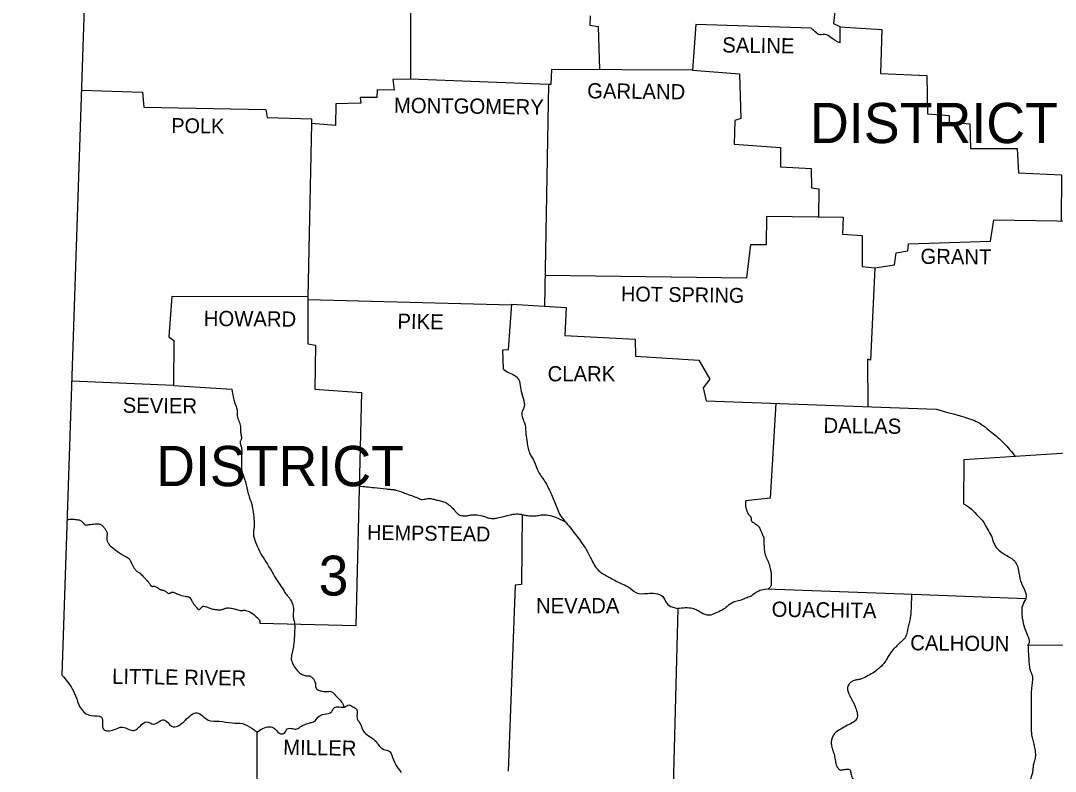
# Model space of a CAD drawing. Extents: x 6028666 to 6031787, y 5366484 to 5368484.
# Drawn here: x 6031108.5 to 6031401.8, y 5367817 to 5368029.7 of the extents above; entities that cross this region are included whole.
import ezdxf

# ---------------------------------------------------------------- set-up
doc = ezdxf.new("R2010")
doc.units = 0
doc.layers.add('2', color=7, linetype='Continuous')

msp = doc.modelspace()

# ---------------------------------------------------------------- linework, layer by layer
at = {"layer": '2'}
msp.add_line((6031258.15, 5368011.6), (6031256.99, 5367948.8), dxfattribs=at)
for points in [[(6031108.45, 5368281.69), (6031129.15, 5368115.5), (6031120.15, 5367844.2)], [(6031219.09, 5368054.06), (6031218.95, 5368013.1), (6031213.95, 5368013), (6031214.35, 5368010), (6031209.55, 5368010.1), (6031209.45, 5368007.9), (6031204.75, 5368007.9), (6031204.85, 5368006.3), (6031197.85, 5368006.1), (6031197.75, 5368000), (6031190.95, 5368000.6), (6031189.85, 5367951.4), (6031151.35, 5367951.5), (6031150.45, 5367940.1), (6031151.85, 5367939.1), (6031151.75, 5367926.3), (6031122.92, 5367927.57)], [(6031372.35, 5368042.9), (6031365.15, 5368043.7), (6031365.45, 5368041), (6031352.35, 5368040.5), (6031351.95, 5368036.6), (6031339.65, 5368035.9), (6031338.95, 5368028.9), (6031340.75, 5368028), (6031340.75, 5368023.4)], [(6031269.95, 5368031.1), (6031269.85, 5368028.4), (6031272.15, 5368028), (6031272.57, 5368015.83)], [(6031332.55, 5368027.6), (6031299.85, 5368028.6), (6031298.95, 5368015.7), (6031258.95, 5368015.9), (6031258.79, 5368011.57)], [(6031340.75, 5368027.94), (6031352.65, 5368027.2), (6031352.25, 5368014.7), (6031365.35, 5368014.2), (6031365.55, 5368003.3), (6031371.75, 5368002.8), (6031371.75, 5368000.9), (6031377.55, 5368000.5), (6031377.75, 5367993.5), (6031390.95, 5367993.5), (6031391.35, 5367986.6), (6031403.55, 5367986), (6031403.45, 5367972.98)], [(6031298.95, 5368015.7), (6031312.25, 5368014.6), (6031312.65, 5368002), (6031310.95, 5368001.4), (6031310.75, 5367994.7), (6031323.85, 5367993.8), (6031323.85, 5367988.3), (6031332.55, 5367987.8), (6031332.65, 5367982.3), (6031334.75, 5367982), (6031334.65, 5367974.1)], [(6031258.15, 5368011.6), (6031218.95, 5368013.1)], [(6031125.65, 5368010), (6031142.95, 5368009.4), (6031143.35, 5368005.2), (6031177.95, 5368004.5), (6031178.35, 5368002.3), (6031190.95, 5368001.9), (6031190.95, 5368000.6)], [(6031258.79, 5368011.57), (6031258.15, 5368011.6)], [(6031257.15, 5367957.6), (6031314.35, 5367956.8), (6031315.45, 5367966.3), (6031319.95, 5367966.3), (6031320.05, 5367974.3), (6031341.65, 5367974), (6031341.45, 5367969.2), (6031347.05, 5367968.8), (6031347.05, 5367960), (6031350.65, 5367959.7), (6031350.61, 5367958.79)], [(6031350.65, 5367959.7), (6031356.25, 5367960.5), (6031356.65, 5367963.9), (6031359.95, 5367964.5), (6031360.15, 5367966.5), (6031383.45, 5367967.2), (6031384.35, 5367973.3), (6031408.25, 5367972.9)], [(6031350.65, 5367959.7), (6031349.45, 5367933.5), (6031348.55, 5367933.8), (6031348.65, 5367920.32)], [(6031189.85, 5367951.4), (6031189.85, 5367938.1), (6031192.05, 5367937.7), (6031191.85, 5367925.3), (6031205.05, 5367924.3), (6031203.45, 5367858.2), (6031176.25, 5367858.9)], [(6031189.85, 5367950.71), (6031247.74, 5367949.19)], [(6031245.35, 5367930.9), (6031245.15, 5367936.4), (6031246.75, 5367936.5), (6031247.75, 5367949.4), (6031263.15, 5367948.4), (6031262.75, 5367940.5), (6031282.65, 5367939.4), (6031282.75, 5367934.6), (6031300.75, 5367933.5), (6031303.85, 5367928.1), (6031301.95, 5367925.7), (6031302.85, 5367922), (6031368.05, 5367919.6)], [(6031151.75, 5367926.3), (6031168.35, 5367925.3)], [(6031322.52, 5367921.28), (6031320.95, 5367894.4), (6031314.05, 5367893.6)], [(6031390.49, 5367906.2), (6031375.85, 5367905.3), (6031375.75, 5367892.8)], [(6031405.05, 5367907.1), (6031390.43, 5367906.2)], [(6031250.65, 5367889.75), (6031250.45, 5367869.9), (6031248.65, 5367869.7), (6031246.65, 5367817)], [(6031319.95, 5367868.7), (6031361.35, 5367867.2), (6031393.47, 5367865.95)], [(6031294.75, 5367863.1), (6031293.45, 5367812.7), (6031279.95, 5367813.6), (6031279.85, 5367809.9), (6031262.06, 5367810.95)], [(6031394.05, 5367852.7), (6031439.25, 5367852.8)], [(6031175.45, 5367828.1), (6031175.65, 5367747.21), (6031542.15, 5367746.61)]]:
    msp.add_lwpolyline(points, dxfattribs=at)
for points in [[(6031340.75, 5368023.4), (6031338.15, 5368024.9), (6031336.65, 5368025.8), (6031335.05, 5368025.7), (6031333.75, 5368026.5), (6031332.55, 5368027.6)], [(6031245.35, 5367930.9), (6031246.95, 5367929.9), (6031248.85, 5367929), (6031249.85, 5367927.5), (6031250.25, 5367925.2), (6031250.95, 5367922.7), (6031251.15, 5367920.1), (6031250.55, 5367918.7), (6031251.35, 5367915.5), (6031251.65, 5367913.3), (6031251.95, 5367910.7), (6031252.75, 5367907.2), (6031254.05, 5367904.8), (6031255.25, 5367901.9), (6031257.25, 5367898.8), (6031258.95, 5367895.4), (6031259.75, 5367893.6), (6031261.25, 5367889.9), (6031263.15, 5367887.4), (6031266.15, 5367883.6), (6031268.85, 5367879.7), (6031270.35, 5367876.8), (6031272.65, 5367873.6), (6031275.25, 5367872), (6031278.55, 5367870.3), (6031280.65, 5367869.3), (6031283.05, 5367867.6), (6031286.15, 5367867.4), (6031288.45, 5367867.4), (6031290.55, 5367866.5), (6031291.55, 5367864.7), (6031293.35, 5367863.5), (6031294.75, 5367863.1)], [(6031168.35, 5367925.3), (6031168.85, 5367922.3), (6031169.04, 5367921.64), (6031169.3, 5367921), (6031169.55, 5367920.36), (6031169.75, 5367919.7), (6031169.81, 5367919.21), (6031169.82, 5367918.7), (6031169.81, 5367918.2), (6031169.85, 5367917.7), (6031170.05, 5367916.95), (6031170.33, 5367916.21), (6031170.59, 5367915.46), (6031170.75, 5367914.7), (6031170.75, 5367913.6), (6031170.81, 5367913.05), (6031170.91, 5367912.5), (6031171, 5367911.95), (6031171.05, 5367911.4), (6031171, 5367911.1), (6031170.86, 5367910.8), (6031170.72, 5367910.5), (6031170.65, 5367910.2), (6031170.74, 5367909.61), (6031170.92, 5367909.01), (6031171.09, 5367908.41), (6031171.15, 5367907.8), (6031171.05, 5367906), (6031171.05, 5367904.5), (6031171.15, 5367902), (6031171.29, 5367901.44), (6031171.52, 5367900.89), (6031171.76, 5367900.35), (6031171.95, 5367899.8), (6031172.75, 5367896.5), (6031173.25, 5367894.8), (6031174.05, 5367892.2), (6031174.55, 5367889), (6031174.65, 5367886.6), (6031174.62, 5367886.05), (6031174.54, 5367885.5), (6031174.47, 5367884.95), (6031174.45, 5367884.4), (6031175.05, 5367881.9), (6031176.15, 5367879.4), (6031177.55, 5367877), (6031179.25, 5367874.3), (6031180.45, 5367872.2), (6031181.95, 5367869.9), (6031183.15, 5367868), (6031183.58, 5367867.39), (6031184.04, 5367866.81), (6031184.51, 5367866.22), (6031184.95, 5367865.6), (6031185.75, 5367863.6), (6031185.8, 5367862.9), (6031185.77, 5367862.2), (6031185.73, 5367861.5), (6031185.75, 5367860.8), (6031185.85, 5367860.15), (6031185.98, 5367859.51), (6031186.1, 5367858.86), (6031186.15, 5367858.2), (6031186.05, 5367855.3), (6031185.85, 5367852.7), (6031185.71, 5367851.8), (6031185.49, 5367850.9), (6031185.28, 5367850), (6031185.15, 5367849.1), (6031185.65, 5367847.4), (6031187.55, 5367844.9), (6031188.75, 5367844.2), (6031189.27, 5367844.08), (6031189.81, 5367844.06), (6031190.35, 5367844.01), (6031190.85, 5367843.8), (6031191.44, 5367843.16), (6031191.85, 5367842.4), (6031192, 5367841.88), (6031192.05, 5367841.3), (6031192.14, 5367840.76), (6031192.26, 5367840.52), (6031192.45, 5367840.3), (6031193.47, 5367839.81), (6031194.55, 5367839.6), (6031194.85, 5367839.57), (6031195.15, 5367839.58), (6031195.78, 5367839.65), (6031196.37, 5367839.65), (6031196.85, 5367839.4), (6031197.95, 5367838.2), (6031199.45, 5367836.6), (6031200.19, 5367835.2)], [(6031368.05, 5367919.6), (6031375.85, 5367917.4), (6031379.85, 5367915.9), (6031383.85, 5367913), (6031387.15, 5367910.1), (6031390.43, 5367906.2)], [(6031204.41, 5367897.8), (6031208.65, 5367897.4), (6031212.15, 5367897), (6031213.51, 5367896.89), (6031214.18, 5367896.83), (6031214.52, 5367896.77), (6031214.85, 5367896.7), (6031215.57, 5367896.49), (6031216.27, 5367896.24), (6031217.65, 5367895.7), (6031220.15, 5367894.8), (6031220.56, 5367894.64), (6031220.95, 5367894.45), (6031221.34, 5367894.26), (6031221.75, 5367894.1), (6031222.42, 5367894.03), (6031223.1, 5367894.15), (6031223.78, 5367894.29), (6031224.45, 5367894.3), (6031225.61, 5367894.08), (6031226.75, 5367893.8), (6031228.09, 5367893.45), (6031228.73, 5367893.22), (6031229.05, 5367893.07), (6031229.35, 5367892.9), (6031230.36, 5367892.1), (6031231.25, 5367891.2), (6031231.54, 5367890.88), (6031231.81, 5367890.54), (6031232.45, 5367889.9), (6031233.01, 5367889.6), (6031233.59, 5367889.45), (6031234.75, 5367889.4), (6031235.23, 5367889.46), (6031235.7, 5367889.56), (6031236.18, 5367889.66), (6031236.65, 5367889.7), (6031238.95, 5367889.5), (6031239.61, 5367889.33), (6031240.26, 5367889.08), (6031240.9, 5367888.85), (6031241.55, 5367888.7), (6031242.08, 5367888.66), (6031242.61, 5367888.66), (6031243.65, 5367888.8), (6031245.35, 5367889.2), (6031247.35, 5367889.7), (6031248.6, 5367889.9), (6031249.23, 5367889.92), (6031249.85, 5367889.9), (6031250.33, 5367889.83), (6031250.8, 5367889.71), (6031251.27, 5367889.59), (6031251.75, 5367889.5), (6031253, 5367889.42), (6031254.25, 5367889.4), (6031254.98, 5367889.46), (6031255.7, 5367889.58), (6031256.43, 5367889.68), (6031256.79, 5367889.71), (6031257.15, 5367889.7), (6031257.89, 5367889.61), (6031260.07, 5367888.98), (6031261.49, 5367888.37), (6031262.88, 5367887.74)], [(6031314.05, 5367893.6), (6031313.94, 5367892.65), (6031313.98, 5367892.17), (6031314.05, 5367891.7), (6031314.17, 5367891.24), (6031314.33, 5367890.78), (6031314.53, 5367890.34), (6031314.75, 5367889.9), (6031314.91, 5367889.68), (6031315.1, 5367889.49), (6031315.29, 5367889.31), (6031315.45, 5367889.1), (6031315.55, 5367888.79), (6031315.57, 5367888.43), (6031315.6, 5367888.09), (6031315.66, 5367887.93), (6031315.75, 5367887.8), (6031315.96, 5367887.63), (6031316.2, 5367887.49), (6031316.43, 5367887.36), (6031316.65, 5367887.2), (6031316.83, 5367887.07), (6031317.01, 5367886.93), (6031317.37, 5367886.66), (6031317.7, 5367886.36), (6031317.84, 5367886.19), (6031317.95, 5367886), (6031318.15, 5367885.58), (6031318.32, 5367885.16), (6031318.48, 5367884.73), (6031318.65, 5367884.3), (6031318.92, 5367883.76), (6031319.05, 5367883.49), (6031319.11, 5367883.35), (6031319.15, 5367883.2), (6031319.2, 5367882.85), (6031319.19, 5367882.5), (6031319.16, 5367882.15), (6031319.15, 5367881.8), (6031319.2, 5367881.1), (6031319.25, 5367880.4), (6031319.33, 5367879.55), (6031319.38, 5367879.13), (6031319.45, 5367878.7), (6031319.68, 5367877.93), (6031320.02, 5367877.19), (6031320.37, 5367876.46), (6031320.65, 5367875.7), (6031320.95, 5367874.5), (6031321.15, 5367873.5), (6031321.25, 5367871.8), (6031321.27, 5367871.3), (6031321.28, 5367870.8), (6031321.27, 5367870.3), (6031321.27, 5367870.05), (6031321.25, 5367869.8), (6031321.17, 5367869.52), (6031320.97, 5367869.21), (6031320.43, 5367868.69)], [(6031375.75, 5367892.8), (6031378.05, 5367891.3), (6031379.95, 5367889.3), (6031381.35, 5367887.8), (6031382.25, 5367886.1), (6031383.45, 5367884.1), (6031385.15, 5367880.3), (6031386.65, 5367879), (6031388.75, 5367877.7), (6031390.05, 5367876.8), (6031391.35, 5367873.9), (6031391.95, 5367871), (6031393.05, 5367868.4), (6031393.55, 5367866.4), (6031392.65, 5367864.4), (6031392.45, 5367860.4), (6031393.05, 5367857.7), (6031393.85, 5367855.7), (6031394.35, 5367853.4), (6031394.05, 5367852.7)], [(6031121.62, 5367888.34), (6031122.63, 5367888.43), (6031123.66, 5367888.41), (6031124.63, 5367888.3), (6031125.45, 5367888.1), (6031125.81, 5367887.82), (6031126.15, 5367887.37), (6031126.52, 5367886.96), (6031126.95, 5367886.8), (6031127.85, 5367886.9), (6031129.45, 5367887.1), (6031129.83, 5367887.13), (6031130.2, 5367887.13), (6031130.58, 5367887.09), (6031130.95, 5367887), (6031131.28, 5367886.85), (6031131.56, 5367886.64), (6031131.81, 5367886.39), (6031132.05, 5367886.1), (6031132.36, 5367885.72), (6031132.62, 5367885.34), (6031132.83, 5367884.94), (6031132.95, 5367884.5), (6031132.97, 5367884.13), (6031132.92, 5367883.75), (6031132.86, 5367883.38), (6031132.85, 5367883), (6031132.95, 5367882.4), (6031133.07, 5367882.04), (6031133.22, 5367881.7), (6031133.65, 5367881.1), (6031134.85, 5367880.1), (6031136.15, 5367879.1), (6031137.35, 5367878.3), (6031137.61, 5367878.15), (6031137.9, 5367878.01), (6031138.47, 5367877.75), (6031138.98, 5367877.44), (6031139.35, 5367877), (6031139.55, 5367876.6), (6031140.35, 5367875), (6031140.8, 5367874.31), (6031141.06, 5367874), (6031141.35, 5367873.7), (6031141.64, 5367873.48), (6031141.96, 5367873.3), (6031142.27, 5367873.12), (6031142.55, 5367872.9), (6031143.85, 5367871.5), (6031144.45, 5367870.9), (6031144.72, 5367870.57), (6031144.94, 5367870.19), (6031145.17, 5367869.83), (6031145.3, 5367869.66), (6031145.45, 5367869.5), (6031145.7, 5367869.4), (6031145.99, 5367869.42), (6031146.28, 5367869.45), (6031146.55, 5367869.4), (6031146.93, 5367869.19), (6031147.3, 5367868.94), (6031147.67, 5367868.7), (6031148.05, 5367868.5), (6031148.32, 5367868.41), (6031148.61, 5367868.35), (6031148.89, 5367868.28), (6031149.15, 5367868.2), (6031149.46, 5367868.03), (6031149.75, 5367867.8), (6031150.04, 5367867.57), (6031150.35, 5367867.4), (6031150.65, 5367867.43), (6031150.95, 5367867.61), (6031151.26, 5367867.78), (6031151.55, 5367867.8), (6031151.93, 5367867.66), (6031152.3, 5367867.5), (6031152.68, 5367867.34), (6031153.05, 5367867.2), (6031155.05, 5367866.6), (6031155.33, 5367866.56), (6031155.62, 5367866.55), (6031156.03, 5367866.47), (6031156.09, 5367866.44), (6031156.15, 5367866.4), (6031156.57, 5367865.99), (6031156.88, 5367865.51), (6031157.15, 5367864.99), (6031157.29, 5367864.74), (6031157.45, 5367864.5), (6031158.07, 5367863.68), (6031158.4, 5367863.28), (6031158.75, 5367862.9), (6031158.93, 5367862.82), (6031159.11, 5367862.88), (6031159.51, 5367863.23), (6031159.92, 5367863.64), (6031160.14, 5367863.78), (6031160.35, 5367863.8), (6031161.09, 5367863.61), (6031161.84, 5367863.34), (6031162.59, 5367863.07), (6031163.35, 5367862.9), (6031164.31, 5367862.8), (6031165.25, 5367862.8), (6031165.68, 5367862.9), (6031166.1, 5367863.06), (6031166.52, 5367863.22), (6031166.95, 5367863.3), (6031168.25, 5367863.2), (6031168.86, 5367863.07), (6031169.45, 5367862.9), (6031170.05, 5367862.73), (6031170.65, 5367862.6), (6031171.02, 5367862.58), (6031171.4, 5367862.6), (6031171.78, 5367862.63), (6031172.15, 5367862.6), (6031173.75, 5367862), (6031175.25, 5367860.8), (6031176.25, 5367859.5), (6031176.25, 5367858.9)], [(6031315.45, 5367866.6), (6031314.73, 5367866.31), (6031313.45, 5367865.8), (6031311.95, 5367865.3), (6031310.55, 5367864.9), (6031308.75, 5367863.7), (6031307.35, 5367862.7), (6031305.45, 5367861.8), (6031303.65, 5367861.2), (6031301.45, 5367861.9), (6031300.25, 5367862.6), (6031298.95, 5367863.1), (6031294.75, 5367863.1)], [(6031315.45, 5367866.6), (6031318.05, 5367868.3), (6031319.95, 5367868.7)], [(6031361.02, 5367867.21), (6031360.95, 5367864.11), (6031360.88, 5367862.55), (6031360.83, 5367861.78), (6031360.75, 5367861), (6031360.45, 5367859.44), (6031360.05, 5367857.9), (6031359.79, 5367856.48), (6031359.62, 5367855.78), (6031359.5, 5367855.44), (6031359.43, 5367855.27), (6031359.35, 5367855.1), (6031359.05, 5367854.64), (6031358.67, 5367854.24), (6031357.85, 5367853.5), (6031357.05, 5367852.71), (6031356.25, 5367851.9), (6031354.75, 5367850.1), (6031354.41, 5367849.57), (6031354.11, 5367849), (6031353.8, 5367848.44), (6031353.45, 5367847.9), (6031352.15, 5367846.5), (6031350.45, 5367845.1), (6031348.75, 5367844.1), (6031346.85, 5367843.2), (6031346.34, 5367843.04), (6031345.81, 5367842.94), (6031345.28, 5367842.85), (6031344.75, 5367842.7), (6031343.92, 5367842.28), (6031343.56, 5367841.98), (6031343.4, 5367841.8), (6031343.25, 5367841.6), (6031342.99, 5367841.02), (6031342.9, 5367840.4), (6031343.15, 5367839.2), (6031343.56, 5367838.35), (6031344.01, 5367837.51), (6031344.45, 5367836.67), (6031344.85, 5367835.8), (6031345.45, 5367834.2), (6031345.59, 5367833.74), (6031345.67, 5367833.26), (6031345.7, 5367832.78), (6031345.65, 5367832.3), (6031344.95, 5367831.2), (6031343.35, 5367830.3), (6031341.45, 5367829.2), (6031339.75, 5367828.2), (6031339.35, 5367827.88), (6031339.02, 5367827.47), (6031338.76, 5367827), (6031338.55, 5367826.5), (6031338.28, 5367825.35), (6031338.35, 5367824.2), (6031338.54, 5367823.53), (6031338.75, 5367822.85), (6031338.97, 5367822.18), (6031339.15, 5367821.5), (6031339.3, 5367820.71), (6031339.45, 5367819.9), (6031339.84, 5367818.49), (6031340.19, 5367817.87), (6031340.44, 5367817.61), (6031340.59, 5367817.5), (6031340.75, 5367817.4), (6031341, 5367817.35), (6031341.25, 5367817.39), (6031341.5, 5367817.46), (6031341.75, 5367817.5), (6031341.98, 5367817.52), (6031342.2, 5367817.55), (6031342.66, 5367817.62), (6031343.11, 5367817.6), (6031343.33, 5367817.53), (6031343.44, 5367817.48), (6031343.55, 5367817.4), (6031343.7, 5367817.17), (6031343.75, 5367816.9), (6031343.85, 5367816.4), (6031344.25, 5367815.1), (6031344.55, 5367814.77), (6031345, 5367814.55), (6031345.45, 5367814.33), (6031345.75, 5367814), (6031345.82, 5367813.76), (6031345.86, 5367813.51), (6031345.89, 5367813.25), (6031345.95, 5367813), (6031346.33, 5367812.03), (6031346.85, 5367811.1), (6031347.17, 5367810.7), (6031347.52, 5367810.34), (6031348.35, 5367809.8), (6031349.45, 5367809.4), (6031351.75, 5367808.7), (6031352.95, 5367808.4), (6031353.12, 5367808.32), (6031353.44, 5367807.84), (6031353.59, 5367806.87), (6031353.75, 5367805.95), (6031353.94, 5367805.64), (6031354.25, 5367805.5), (6031355.05, 5367805.51), (6031355.85, 5367805.6), (6031357.05, 5367805.8), (6031358.06, 5367805.76), (6031358.56, 5367805.59), (6031358.81, 5367805.46), (6031359.05, 5367805.3), (6031359.59, 5367804.74), (6031359.95, 5367804.1), (6031360.19, 5367803.61), (6031360.4, 5367803.11), (6031360.61, 5367802.6), (6031360.85, 5367802.1), (6031361.38, 5367801.34), (6031361.66, 5367801.04)], [(6031394.05, 5367852.7), (6031394.13, 5367851.15), (6031394.22, 5367849.6), (6031394.45, 5367846.5), (6031394.63, 5367845.74), (6031394.94, 5367845), (6031395.23, 5367844.26), (6031395.32, 5367843.89), (6031395.35, 5367843.5), (6031395.31, 5367842.71), (6031395.21, 5367841.91), (6031395.12, 5367841.11), (6031395.05, 5367840.3), (6031394.95, 5367837.2), (6031394.95, 5367834.4), (6031394.95, 5367831.7), (6031394.95, 5367828.9), (6031395.15, 5367826.9), (6031395.3, 5367826.17), (6031395.49, 5367825.45), (6031395.68, 5367824.73), (6031395.85, 5367824), (6031396.1, 5367822.65), (6031396.16, 5367821.98), (6031396.15, 5367821.3), (6031396.05, 5367820.65), (6031395.88, 5367820), (6031395.7, 5367819.35), (6031395.55, 5367818.7), (6031395.48, 5367818.11), (6031395.43, 5367817.5), (6031395.36, 5367816.9), (6031395.25, 5367816.3), (6031395.07, 5367815.7), (6031394.86, 5367815.1), (6031394.64, 5367814.51), (6031394.45, 5367813.9), (6031393.75, 5367811.2), (6031392.95, 5367807.7), (6031392.64, 5367806.54), (6031392.46, 5367805.97), (6031392.25, 5367805.4), (6031391.95, 5367804.78), (6031391.58, 5367804.19), (6031391.2, 5367803.6), (6031390.85, 5367803), (6031390.61, 5367802.46), (6031390.4, 5367801.91), (6031390.19, 5367801.35), (6031389.95, 5367800.8), (6031389.64, 5367800.43), (6031389.23, 5367800.13), (6031388.82, 5367799.82), (6031388.66, 5367799.63), (6031388.55, 5367799.4), (6031388.33, 5367798.21), (6031388.35, 5367797), (6031388.42, 5367796.45), (6031388.51, 5367795.9), (6031388.6, 5367795.35), (6031388.65, 5367794.8), (6031388.63, 5367794.31), (6031388.56, 5367793.81), (6031388.48, 5367793.3), (6031388.45, 5367792.8), (6031388.63, 5367791.84), (6031389.15, 5367790.9), (6031389.49, 5367790.5), (6031389.85, 5367790.11), (6031390.58, 5367789.61)], [(6031120.15, 5367844.2), (6031123.05, 5367840.4), (6031124.25, 5367837.7), (6031125.95, 5367834.2), (6031128.45, 5367832.8), (6031131.35, 5367832.3), (6031131.95, 5367828.9), (6031134.95, 5367828.8), (6031137.35, 5367829.5), (6031140.65, 5367828.6), (6031144.15, 5367831), (6031146.15, 5367830.4), (6031149.05, 5367831.6), (6031151.25, 5367829.8), (6031155.05, 5367831.4), (6031158.45, 5367833.6), (6031161.65, 5367831.5), (6031164.75, 5367831.2), (6031168.45, 5367830.7), (6031171.35, 5367830.5), (6031173.95, 5367829.2), (6031175.26, 5367828.3), (6031175.45, 5367828.1)], [(6031175.45, 5367828.1), (6031178.95, 5367829.6), (6031180.45, 5367829.1), (6031181.75, 5367827.8), (6031183.25, 5367827.8), (6031184.05, 5367829), (6031185.55, 5367829.1), (6031186.75, 5367829), (6031188.05, 5367829.8), (6031189.15, 5367830.3), (6031190.65, 5367830.8), (6031191.75, 5367831.2), (6031192.75, 5367832.3), (6031194.55, 5367833.2), (6031196.65, 5367833.9), (6031197.25, 5367834.9), (6031198.25, 5367835.3), (6031200.25, 5367835.2), (6031201.55, 5367835.8), (6031202.65, 5367835.3), (6031203.65, 5367834.6), (6031203.85, 5367832), (6031204.65, 5367830.6), (6031205.85, 5367828.1), (6031207.55, 5367826.8), (6031209.15, 5367825.5), (6031209.75, 5367824.7), (6031211.45, 5367823.2), (6031212.95, 5367822.7), (6031213.65, 5367821.6), (6031214.75, 5367819), (6031216.35, 5367816.7)]]:
    msp.add_spline(points, degree=3, dxfattribs=at)

# ---------------------------------------------------------------- texts
for s, height, rotation, p in [('SALINE', 4.301, 359.1492, (6031307.35, 5368020.7)), ('GARLAND', 4.301, 359.3658, (6031269.05, 5368007.7)), ('MONTGOMERY', 4.301, 359.2944, (6031214.25, 5368003.6)), ('POLK', 4.199, 359.2152, (6031151.15, 5367997.9)), ('GRANT', 4.301, 359.4032, (6031363.55, 5367960.8)), ('HOT SPRING', 4.2, 359.2216, (6031278.65, 5367950.2)), ('HOWARD', 4.301, 359.5145, (6031160.35, 5367943.2)), ('PIKE', 4.299, 359.0452, (6031215.25, 5367942.4)), ('SEVIER', 4.301, 359.4271, (6031137.35, 5367918.6)), ('DALLAS', 4.299, 359.2462, (6031336.05, 5367912.9)), ('HEMPSTEAD', 4.199, 359.1885, (6031206.65, 5367882.6)), ('OUACHITA', 4.301, 359.2043, (6031321.35, 5367860.8)), ('CALHOUN', 4.301, 359.3634, (6031360.65, 5367851.3)), ('LITTLE RIVER', 4.3006, 359.1697, (6031134.35, 5367841.8)), ('MILLER', 4.299, 359.132, (6031182.85, 5367821.7))]:
    msp.add_text(s, height=height, rotation=rotation, dxfattribs=at).set_placement(p)
for s, height, p in [('DISTRICT 6', 11.4, (6031332.25, 5367995)), ('CLARK', 4.3, (6031257.85, 5367927.5)), ('DISTRICT', 11.4, (6031146.85, 5367897.8)), ('3', 11.3, (6031192.95, 5367866.8)), ('NEVADA', 4.3, (6031254.55, 5367861.8))]:
    msp.add_text(s, height=height, dxfattribs=at).set_placement(p)

doc.saveas('drawing.dxf')
